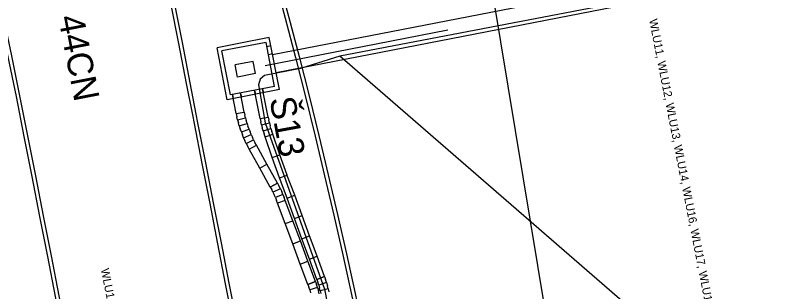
# Model space of a CAD drawing. Extents: x -545258 to -544992, y -1122311 to -1121664.
# Drawn here: x -545186.13 to -545148.94, y -1121746.97 to -1121733.41 of the extents above; entities that cross this region are included whole.
import ezdxf

# ---------------------------------------------------------------- set-up
doc = ezdxf.new("R2010")
doc.units = 0
for name, color, linetype in [('SO 18-01-01_3', 7, 'Continuous'), ('SO 18-01-01_4', 7, 'Continuous'), ('SO18-15-08', 7, 'Continuous'), ('SO18-15-08_def', 7, 'Continuous'), ('SO18-16-02', 7, 'Continuous'), ('so180605', 7, 'Continuous'), ('SOPS', 7, 'Continuous')]:
    doc.layers.add(name, color=color, linetype=linetype)

msp = doc.modelspace()

# ---------------------------------------------------------------- linework, layer by layer
at = {"layer": 'SO 18-01-01_4'}
msp.add_lwpolyline([(-545102.793, -1122250.491), (-545106.116, -1122208.618), (-545109.928, -1122137.596), (-545106.412, -1122088.188), (-545106.367, -1122023.596), (-545108.703, -1121978.559), (-545127.424, -1121916.593), (-545139.015, -1121857.213), (-545147.82, -1121812.064), (-545159.299, -1121753.172), (-545170.035, -1121688.35), (-545174.127, -1121676.058)], dxfattribs=at)
at = {"layer": 'SO18-15-08_def'}
for p, q in [((-545173.529, -1121735.342), (-545133.547, -1121727.549)), ((-545173.358, -1121736.219), (-545133.375, -1121728.432)), ((-545173.194, -1121737.06), (-545173.692, -1121734.508)), ((-545173.429, -1121736.902), (-545173.85, -1121734.743)), ((-545173.811, -1121734.939), (-545173.615, -1121734.9)), ((-545175.746, -1121737.557), (-545176.243, -1121735.005)), ((-545175.588, -1121737.323), (-545176.009, -1121735.163)), ((-545173.735, -1121735.331), (-545173.538, -1121735.293)), ((-545174.367, -1121736.27), (-545174.482, -1121735.681)), ((-545175.25, -1121736.442), (-545175.365, -1121735.853)), ((-545174.41, -1121737.093), (-545174.372, -1121737.289)), ((-545174.14, -1121738.479), (-545174.41, -1121737.093)), ((-545174.018, -1121737.017), (-545173.979, -1121737.213)), ((-545173.747, -1121738.403), (-545174.018, -1121737.017)), ((-545175.309, -1121738.233), (-545175.49, -1121737.304)), ((-545175.49, -1121737.304), (-545175.452, -1121737.5)), ((-545174.916, -1121738.157), (-545175.097, -1121737.227)), ((-545175.097, -1121737.227), (-545175.059, -1121737.423)), ((-545175.309, -1121738.233), (-545174.916, -1121738.157)), ((-545175.309, -1121738.233), (-545175.279, -1121738.386)), ((-545174.916, -1121738.157), (-545174.888, -1121738.299)), ((-545174.853, -1121738.44), (-545174.888, -1121738.299)), ((-545175.241, -1121738.537), (-545175.279, -1121738.386)), ((-545175.241, -1121738.537), (-545174.853, -1121738.44)), ((-545175.241, -1121738.537), (-545175.204, -1121738.687)), ((-545174.853, -1121738.44), (-545174.818, -1121738.58)), ((-545174.775, -1121738.719), (-545174.818, -1121738.58)), ((-545174.14, -1121738.479), (-545173.747, -1121738.403)), ((-545174.14, -1121738.479), (-545174.11, -1121738.632)), ((-545174.073, -1121738.783), (-545174.11, -1121738.632)), ((-545174.073, -1121738.783), (-545173.684, -1121738.686)), ((-545173.747, -1121738.403), (-545173.72, -1121738.545)), ((-545173.684, -1121738.686), (-545173.72, -1121738.545)), ((-545173.684, -1121738.686), (-545173.649, -1121738.826)), ((-545175.158, -1121738.836), (-545175.204, -1121738.687)), ((-545175.158, -1121738.836), (-545174.775, -1121738.719)), ((-545175.158, -1121738.836), (-545175.112, -1121738.985)), ((-545175.059, -1121739.131), (-545175.112, -1121738.985)), ((-545175.059, -1121739.131), (-545174.683, -1121738.994)), ((-545175.059, -1121739.131), (-545174.683, -1121738.994)), ((-545174.775, -1121738.719), (-545174.733, -1121738.858)), ((-545174.683, -1121738.994), (-545174.733, -1121738.858)), ((-545174.683, -1121738.994), (-545174.634, -1121739.13)), ((-545174.073, -1121738.783), (-545174.035, -1121738.933)), ((-545173.989, -1121739.082), (-545174.035, -1121738.933)), ((-545173.989, -1121739.082), (-545173.607, -1121738.965)), ((-545173.607, -1121738.965), (-545173.649, -1121738.826)), ((-545173.607, -1121738.965), (-545173.564, -1121739.104)), ((-545175.059, -1121739.131), (-545175.006, -1121739.277)), ((-545174.945, -1121739.42), (-545175.006, -1121739.277)), ((-545174.945, -1121739.42), (-545174.577, -1121739.264)), ((-545174.945, -1121739.42), (-545174.884, -1121739.563)), ((-545174.577, -1121739.264), (-545174.634, -1121739.13)), ((-545174.577, -1121739.264), (-545174.52, -1121739.397)), ((-545174.457, -1121739.527), (-545174.52, -1121739.397)), ((-545173.989, -1121739.082), (-545173.944, -1121739.231)), ((-545173.891, -1121739.377), (-545173.944, -1121739.231)), ((-545173.891, -1121739.377), (-545173.515, -1121739.24)), ((-545173.545, -1121740.379), (-545173.891, -1121739.377)), ((-545173.515, -1121739.24), (-545173.564, -1121739.104)), ((-545173.167, -1121740.248), (-545173.512, -1121739.246)), ((-545174.816, -1121739.703), (-545174.884, -1121739.563)), ((-545174.816, -1121739.703), (-545174.457, -1121739.527)), ((-545174.816, -1121739.703), (-545174.748, -1121739.843)), ((-545174.672, -1121739.978), (-545174.323, -1121739.784)), ((-545174.457, -1121739.527), (-545174.393, -1121739.658)), ((-545174.323, -1121739.784), (-545174.393, -1121739.658)), ((-545173.808, -1121740.711), (-545174.323, -1121739.784)), ((-545174.672, -1121739.978), (-545174.748, -1121739.843)), ((-545174.158, -1121740.905), (-545174.672, -1121739.978)), ((-545173.545, -1121740.379), (-545173.167, -1121740.248)), ((-545173.199, -1121741.381), (-545173.545, -1121740.379)), ((-545172.821, -1121741.25), (-545173.167, -1121740.248)), ((-545174.158, -1121740.905), (-545173.808, -1121740.711)), ((-545173.644, -1121741.832), (-545174.158, -1121740.905)), ((-545173.294, -1121741.638), (-545173.808, -1121740.711)), ((-545173.199, -1121741.381), (-545172.821, -1121741.25)), ((-545172.446, -1121742.227), (-545172.826, -1121741.237)), ((-545173.644, -1121741.832), (-545173.294, -1121741.638)), ((-545173.294, -1121741.638), (-545173.644, -1121741.832)), ((-545173.294, -1121741.638), (-545173.219, -1121741.774)), ((-545172.819, -1121742.37), (-545173.199, -1121741.381)), ((-545173.644, -1121741.832), (-545173.573, -1121741.959)), ((-545173.51, -1121742.089), (-545173.573, -1121741.959)), ((-545173.15, -1121741.914), (-545173.51, -1121742.089)), ((-545173.15, -1121741.914), (-545173.219, -1121741.774)), ((-545173.15, -1121741.914), (-545173.082, -1121742.053)), ((-545173.51, -1121742.089), (-545173.446, -1121742.22)), ((-545173.389, -1121742.353), (-545173.446, -1121742.22)), ((-545173.021, -1121742.196), (-545173.389, -1121742.353)), ((-545173.389, -1121742.353), (-545173.333, -1121742.486)), ((-545173.021, -1121742.196), (-545173.082, -1121742.053)), ((-545173.021, -1121742.196), (-545172.961, -1121742.339)), ((-545172.907, -1121742.485), (-545172.961, -1121742.339)), ((-545172.819, -1121742.37), (-545172.446, -1121742.227)), ((-545172.455, -1121743.371), (-545172.818, -1121742.375)), ((-545172.079, -1121743.234), (-545172.442, -1121742.238)), ((-545173.283, -1121742.622), (-545173.333, -1121742.486)), ((-545172.907, -1121742.485), (-545173.283, -1121742.622)), ((-545172.92, -1121743.618), (-545173.283, -1121742.622)), ((-545172.544, -1121743.481), (-545172.907, -1121742.485)), ((-545172.92, -1121743.618), (-545172.544, -1121743.481)), ((-545172.164, -1121744.471), (-545172.544, -1121743.481)), ((-545172.455, -1121743.371), (-545172.079, -1121743.234)), ((-545172.092, -1121744.367), (-545172.455, -1121743.371)), ((-545171.716, -1121744.23), (-545172.079, -1121743.234)), ((-545172.537, -1121744.614), (-545172.918, -1121743.625)), ((-545172.092, -1121744.367), (-545171.716, -1121744.23)), ((-545171.353, -1121745.226), (-545171.716, -1121744.23)), ((-545172.177, -1121745.604), (-545172.54, -1121744.608)), ((-545172.537, -1121744.614), (-545172.164, -1121744.471)), ((-545171.801, -1121745.467), (-545172.164, -1121744.471)), ((-545171.729, -1121745.363), (-545172.092, -1121744.367)), ((-545171.729, -1121745.363), (-545171.353, -1121745.226)), ((-545171.366, -1121746.359), (-545171.729, -1121745.363)), ((-545170.99, -1121746.222), (-545171.353, -1121745.226)), ((-545172.177, -1121745.604), (-545171.801, -1121745.467)), ((-545171.801, -1121746.604), (-545172.174, -1121745.611)), ((-545171.427, -1121746.463), (-545171.799, -1121745.471)), ((-545171.427, -1121746.463), (-545171.803, -1121746.6)), ((-545171.801, -1121746.604), (-545171.427, -1121746.463)), ((-545171.427, -1121746.463), (-545171.373, -1121746.61)), ((-545171.366, -1121746.359), (-545170.99, -1121746.222)), ((-545170.99, -1121746.222), (-545171.366, -1121746.359)), ((-545171.366, -1121746.359), (-545171.316, -1121746.495)), ((-545171.273, -1121746.633), (-545171.316, -1121746.495)), ((-545170.99, -1121746.222), (-545170.937, -1121746.367)), ((-545170.891, -1121746.516), (-545170.937, -1121746.367)), ((-545171.803, -1121746.6), (-545171.753, -1121746.737)), ((-545171.71, -1121746.875), (-545171.753, -1121746.737)), ((-545171.328, -1121746.758), (-545171.71, -1121746.875)), ((-545171.328, -1121746.758), (-545171.71, -1121746.875)), ((-545171.328, -1121746.758), (-545171.373, -1121746.61)), ((-545171.328, -1121746.758), (-545171.283, -1121746.906)), ((-545170.891, -1121746.516), (-545171.273, -1121746.633)), ((-545171.273, -1121746.633), (-545171.231, -1121746.772)), ((-545171.196, -1121746.913), (-545171.231, -1121746.772)), ((-545170.808, -1121746.816), (-545171.196, -1121746.913)), ((-545170.891, -1121746.516), (-545170.845, -1121746.665)), ((-545170.808, -1121746.816), (-545170.845, -1121746.665)), ((-545170.808, -1121746.816), (-545170.77, -1121746.966)), ((-545171.71, -1121746.875), (-545171.668, -1121747.014)), ((-545171.245, -1121747.058), (-545171.283, -1121746.906)), ((-545171.196, -1121746.913), (-545171.161, -1121747.053))]:
    msp.add_line(p, q, dxfattribs=at)
for points in [[(-545173.894, -1121735.872), (-545164.945, -1121734.127)], [(-545173.894, -1121735.872), (-545164.945, -1121734.128)], [(-545173.692, -1121734.508), (-545175.181, -1121734.798), (-545176.243, -1121735.005)], [(-545173.85, -1121734.743), (-545175.142, -1121734.994), (-545176.009, -1121735.163)], [(-545174.482, -1121735.681), (-545175.365, -1121735.853)], [(-545174.367, -1121736.27), (-545175.25, -1121736.442)], [(-545173.194, -1121737.06), (-545175.746, -1121737.557)], [(-545173.429, -1121736.902), (-545175.588, -1121737.323)]]:
    msp.add_lwpolyline(points, dxfattribs=at)
msp.add_arc((-545183.833, -1121738.93), 10, 11.030192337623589, 11.030232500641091, dxfattribs=at)
at = {"layer": 'SO18-16-02'}
for points in [[(-545176.945, -1121719.669), (-545176.776, -1121720.2), (-545176.186, -1121722.098), (-545175.608, -1121724), (-545175.042, -1121725.905), (-545174.49, -1121727.814), (-545173.95, -1121729.727), (-545173.423, -1121731.644), (-545172.909, -1121733.564), (-545172.407, -1121735.487), (-545171.919, -1121737.414), (-545171.443, -1121739.343), (-545170.98, -1121741.276), (-545170.53, -1121743.212), (-545170.093, -1121745.151), (-545169.669, -1121747.093), (-545169.258, -1121749.038), (-545168.859, -1121750.985), (-545168.519, -1121752.704), (-545168.474, -1121752.936), (-545168.091, -1121754.899), (-545167.708, -1121756.862), (-545167.326, -1121758.825), (-545167.236, -1121759.284)], [(-545176.774, -1121719.615), (-545176.605, -1121720.146), (-545176.014, -1121722.045), (-545175.435, -1121723.948), (-545174.87, -1121725.855), (-545174.317, -1121727.765), (-545173.777, -1121729.679), (-545173.249, -1121731.597), (-545172.735, -1121733.518), (-545172.233, -1121735.442), (-545171.744, -1121737.37), (-545171.268, -1121739.301), (-545170.805, -1121741.235), (-545170.354, -1121743.172), (-545169.917, -1121745.112), (-545169.493, -1121747.055), (-545169.081, -1121749.001), (-545168.683, -1121750.95), (-545168.342, -1121752.67), (-545168.297, -1121752.902), (-545167.914, -1121754.865), (-545167.532, -1121756.828), (-545167.149, -1121758.791), (-545167.06, -1121759.249)], [(-545177.439, -1121738.302), (-545177.741, -1121736.755), (-545178.124, -1121734.792), (-545178.506, -1121732.829), (-545178.889, -1121730.866), (-545179.271, -1121728.903), (-545179.654, -1121726.939), (-545180.037, -1121724.976), (-545180.419, -1121723.013), (-545180.802, -1121721.05), (-545180.924, -1121720.424)], [(-545177.263, -1121738.268), (-545177.564, -1121736.72), (-545177.947, -1121734.757), (-545178.329, -1121732.794), (-545178.712, -1121730.831), (-545179.095, -1121728.868), (-545179.477, -1121726.905), (-545179.86, -1121724.942), (-545180.243, -1121722.979), (-545180.625, -1121721.016), (-545180.747, -1121720.389)], [(-545185.298, -1121741.315), (-545185.41, -1121740.742), (-545185.683, -1121739.352), (-545186.073, -1121737.398), (-545186.472, -1121735.446), (-545186.878, -1121733.495), (-545187.292, -1121731.546)], [(-545185.121, -1121741.281), (-545185.233, -1121740.707), (-545185.506, -1121739.317), (-545185.897, -1121737.362), (-545186.296, -1121735.409), (-545186.702, -1121733.458), (-545187.116, -1121731.508)], [(-545170.712, -1121772.811), (-545171.236, -1121770.127), (-545171.618, -1121768.164), (-545172.001, -1121766.201), (-545172.384, -1121764.237), (-545172.766, -1121762.274), (-545173.149, -1121760.311), (-545173.532, -1121758.348), (-545173.914, -1121756.385), (-545174.297, -1121754.422), (-545174.68, -1121752.459), (-545175.062, -1121750.496), (-545175.445, -1121748.533), (-545175.828, -1121746.57), (-545176.21, -1121744.607), (-545176.593, -1121742.644), (-545176.976, -1121740.681), (-545177.358, -1121738.718), (-545177.439, -1121738.302)], [(-545170.712, -1121772.811), (-545171.236, -1121770.127), (-545171.618, -1121768.164), (-545172.001, -1121766.201), (-545172.384, -1121764.237), (-545172.766, -1121762.274), (-545173.149, -1121760.311), (-545173.532, -1121758.348), (-545173.914, -1121756.385), (-545174.297, -1121754.422), (-545174.68, -1121752.459), (-545175.062, -1121750.496), (-545175.445, -1121748.533), (-545175.828, -1121746.57), (-545176.21, -1121744.607), (-545176.593, -1121742.644), (-545176.976, -1121740.681), (-545177.358, -1121738.718), (-545177.439, -1121738.302)], [(-545170.536, -1121772.777), (-545171.059, -1121770.092), (-545171.442, -1121768.129), (-545171.824, -1121766.166), (-545172.207, -1121764.203), (-545172.59, -1121762.24), (-545172.972, -1121760.277), (-545173.355, -1121758.314), (-545173.738, -1121756.351), (-545174.12, -1121754.388), (-545174.503, -1121752.425), (-545174.886, -1121750.462), (-545175.268, -1121748.499), (-545175.651, -1121746.536), (-545176.034, -1121744.573), (-545176.416, -1121742.609), (-545176.799, -1121740.646), (-545177.182, -1121738.683), (-545177.263, -1121738.268)], [(-545170.536, -1121772.777), (-545171.059, -1121770.092), (-545171.442, -1121768.129), (-545171.824, -1121766.166), (-545172.207, -1121764.203), (-545172.59, -1121762.24), (-545172.972, -1121760.277), (-545173.355, -1121758.314), (-545173.738, -1121756.351), (-545174.12, -1121754.388), (-545174.503, -1121752.425), (-545174.886, -1121750.462), (-545175.268, -1121748.499), (-545175.651, -1121746.536), (-545176.034, -1121744.573), (-545176.416, -1121742.609), (-545176.799, -1121740.646), (-545177.182, -1121738.683), (-545177.263, -1121738.268)], [(-545178.673, -1121774.363), (-545179, -1121772.684), (-545179.383, -1121770.721), (-545179.765, -1121768.758), (-545180.148, -1121766.795), (-545180.531, -1121764.832), (-545180.913, -1121762.869), (-545181.296, -1121760.905), (-545181.678, -1121758.942), (-545182.061, -1121756.979), (-545182.444, -1121755.016), (-545182.826, -1121753.053), (-545183.209, -1121751.09), (-545183.592, -1121749.127), (-545183.974, -1121747.164), (-545184.357, -1121745.201), (-545184.74, -1121743.238), (-545185.121, -1121741.281)], [(-545178.849, -1121774.397), (-545179.177, -1121772.718), (-545179.559, -1121770.755), (-545179.942, -1121768.792), (-545180.325, -1121766.829), (-545180.707, -1121764.866), (-545181.09, -1121762.903), (-545181.473, -1121760.94), (-545181.855, -1121758.977), (-545182.238, -1121757.014), (-545182.62, -1121755.051), (-545183.003, -1121753.088), (-545183.386, -1121751.125), (-545183.768, -1121749.162), (-545184.151, -1121747.198), (-545184.534, -1121745.235), (-545184.916, -1121743.272), (-545185.298, -1121741.315)]]:
    msp.add_lwpolyline(points, dxfattribs=at)
at = {"layer": 'so180605'}
msp.add_lwpolyline([(-545132.254, -1121728.144), (-545170.233, -1121735.416), (-545172.158, -1121736.03), (-545173.921, -1121736.374), (-545174.137, -1121736.554), (-545174.212, -1121736.825), (-545173.896, -1121738.689), (-545170.989, -1121746.837), (-545167.518, -1121764.555), (-545167.361, -1121766.192), (-545166.792, -1121769.109), (-545170.023, -1121769.74), (-545174.029, -1121770.064), (-545176.389, -1121770.5), (-545179.978, -1121771.614), (-545184.305, -1121772.446), (-545187.786, -1121772.724)], dxfattribs=at)
at = {"layer": 'SOPS'}
msp.add_line((-545117.183, -1121781.471), (-545170.233, -1121735.416), dxfattribs=at)

# ---------------------------------------------------------------- texts
at = {"layer": 'SO 18-01-01_3'}
msp.add_text('44CN', height=1.25, rotation=280.9571, dxfattribs=at).set_placement((-545184.027, -1121733.515))
at = {"layer": 'SO18-15-08'}
for s, p in [('WLU11, WLU12, WLU13, WLU14, WLU16, WLU17, WLU19, WLU21, WLU61, WLU62, WLU63, WLU64,WLU65', (-545155.101, -1121733.639)), ('WLU11, WLU12, WLU13, WLU14, WLU16, WLU17, WLU19, WLU61, WLU62, WLU63, WLU64, WLU74', (-545181.938, -1121745.861))]:
    msp.add_text(s, height=0.4032, rotation=281.121, dxfattribs=at).set_placement(p)
at = {"layer": 'SO18-15-08_def'}
msp.add_text('Š13', height=1.25, rotation=280.4462, dxfattribs=at).set_placement((-545173.686, -1121737.514))

doc.saveas('drawing.dxf')
